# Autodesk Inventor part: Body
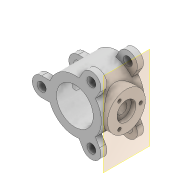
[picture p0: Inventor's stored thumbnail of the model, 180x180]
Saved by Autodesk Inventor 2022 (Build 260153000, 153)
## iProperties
Created: 2019-03
Part Number: Body
Material: Generic
Document SubType Name: Modeling
Designer: LENOVO-CADCIM
Density: 1 g/cm^3
Appearance: Default
Author: LENOVO-CADCIM
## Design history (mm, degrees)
sketch "Sketch1"
  geometry: C1 r 140 at (0, 0); C2 r 97 at (0, 0); 1 further point
  constraints: 2 centre point, 2 coincident
  dimensions: "d0" = 194 diameter of C2; "d1" = 280 diameter of C1
extrude "Extrusion1" new body sketch "Sketch1" stored distance "d2" = 225; taper "d3" = 0 deg
sketch "Sketch2"
  geometry: L1 (0, 0)-(-428, 0); L2 (-130.767, 50)-(-175, 50); L3 (-130.767, -50)-(-175, -50); C1 r 23.5 at (-175, 0); A1 r 175 centre (0, 0) between (-175, 0) and (-175, 0); A2 r 140 centre (0, 0) between (-130.767, 50) and (-130.767, -50) reference; A3 r 50 centre (-175, 0) between (-175, 50) and (-175, -50); 1 further point
  constraints: 6 end point, 6 point on circle, 3 centre point, 3 horizontal, 2 tangent, 1 coincident, 1 point on line, 1 other
  dimensions: "d4" = 350 diameter of A1; "d5" = 50 radius of A3; "d6" = 47 diameter of C1
extrude "Extrusion2" join sketch "Sketch2" distance "d7" = 32; taper "d8" = 0 deg
pattern_circular "Circular Pattern1" dims angle "d10" = 360 deg
mirror "Mirror1"
workplane "Work Plane1"
sketch "Sketch3"
  geometry: C1 r 100 at (0, 0); 1 further point
  constraints: 1 centre point, 1 coincident
  dimensions: "d13" = 200 diameter of C1
extrude "Extrusion3" join sketch "Sketch3" stored distance "d14" = 32; taper "d15" = 0 deg; dims "d4" = 350, "d5" = 50, "d6" = 47
sketch "Sketch4" dims "d16" = 150
  geometry: L1 (0, 0)-(102, 0); 2 further points
  constraints: 2 end point, 1 coincident, 1 horizontal, 1 horizontal alignment, 1 point on line, 2 other
hole "Hole1" sketch "Sketch4" at (75, 0) diameter "d17" = 18.376; stored, may be unused: countersink angle "d21" = 90 deg, drill point angle "d23" = 118 deg; dims "d18" = 40, "d19" = 4, "d20" = 2, "d22" = 47.3
pattern_circular "Circular Pattern2" dims angle "d25" = 360 deg
sketch "Sketch5"
  geometry: C1 r 100 at (0, 0) reference; 2 further points
  constraints: 1 coincident
hole "Hole2" sketch "Sketch5" at (0, 0) diameter "d27" = 56; stored, may be unused: countersink angle "d31" = 90 deg, drill point angle "d33" = 118 deg; dims "d28" = 6, "d29" = 100, "d30" = 25, "d32" = 310
body "Solid1"
